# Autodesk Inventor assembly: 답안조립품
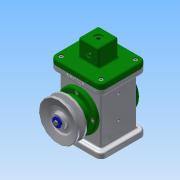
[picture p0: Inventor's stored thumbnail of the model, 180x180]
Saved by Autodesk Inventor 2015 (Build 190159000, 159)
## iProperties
Created: 2017-08
Part Number: 답안조립품
Document SubType Name: Assembly
Designer: Administrator
Author: Administrator
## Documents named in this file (18)
- C:\Users\Administrator\Desktop\470807V1010\답안조립품.iam
- C:\Users\Administrator\Desktop\470807V1010\본체.ipt
- C:\Users\Administrator\Desktop\470807V1010\덮개.ipt
- C:\Users\Administrator\Desktop\470807V1010\앞커버.ipt
- C:\Users\Administrator\Desktop\470807V1010\뒤커버.ipt
- C:\Users\Administrator\Desktop\470807V1010\편심축.ipt
- C:\Users\Administrator\Desktop\470807V1010\베어링 17 x 40 x 12.ipt
- C:\Users\Administrator\Desktop\470807V1010\링크.ipt
- C:\Users\Administrator\Desktop\470807V1010\슬라이더.ipt
- C:\Users\Administrator\Desktop\470807V1010\클레비스 핀 6 x 22.ipt
- 클레비스 핀 6 x 22.ipt
- C:\Users\Administrator\Desktop\470807V1010\E-링.ipt
- C:\Users\Administrator\Desktop\470807V1010\오일 실 17 30 8.ipt
- C:\Users\Administrator\Desktop\470807V1010\키 4 x 4 x 12.ipt
- C:\Users\Administrator\Desktop\470807V1010\V-벨트풀리.ipt
- C:\Users\Administrator\Desktop\470807V1010\와셔 4x16.ipt
- C:\Users\Administrator\Desktop\470807V1010\볼트 M4 x 10.ipt
- C:\Users\Administrator\Desktop\470807V1010\볼트 M4 x 8.ipt
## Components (2 placed, 2 different names)
1. E-링:1
2. V-벨트풀리:1
